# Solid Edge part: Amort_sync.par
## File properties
Author: KULL
Template: Iso Metric Part.par
Last saved by: KULL
Revision: 11
Application: Solid Edge
Accuracy: 0,990
Face Style: Model Default
Fill Style: Normal
Coef. of Thermal Exp: 0.0
Thermal Conductivity: 0.0
Specific Heat: 0.0
Modulus of Elasticity: 0.0
Poisson's Ratio: 0.0
Yield Stress: 0.0
Ultimate Stress: 0.0
Elongation: 0.0
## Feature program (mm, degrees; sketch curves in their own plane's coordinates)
base feature "unnamed BaseFeature 1"
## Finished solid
Body 1: sheet body, 2 faces, 39 edges, 38 vertices.
  Faces by surface: plane 2
  Edges by curve: line 21, circle 18
Body 2: solid body, 53 faces, 87 edges, 36 vertices.
  Faces by surface: torus 17, plane 16, cylinder 14, blend 4, sphere 2
  Edges by curve: circle 59, line 16, intersection 12
Bounding box of the edges (mm; curved faces can reach further): 16.000 x 31.352 x 49.821, from (-8, 49.3583, 6.9663) to (8, 80.7104, 56.7877).
Cylindrical faces by radius (mm): R0.8 x4, R1.5 x3, R2 x2, R3 x2, R4 x1, R8 x2
Toroidal faces (ring radius, tube radius in mm): R1.1 r0.4 x2, R2.2 r0.8 x2, R5.8516 r1.2 x2, R6 r4 x1, R7.2 r0.8 x2, R7.8 r0.2 x2, R21.2565 r0.8 x4, R23.3814 r0.8 x2
Spherical faces by radius (mm): R23.0491 x2
Planar faces by outward normal: +x 3, -x 3, oblique 10
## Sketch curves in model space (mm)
circle centre (0, 59.9207, 39.7682) radius 4
circle centre (0, 73.196, 15.5693) radius 3
line (0, 73.196, 15.5693) -> (0, 59.9207, 39.7682)
line (0, 66.5584, 27.6687) -> (0, 78.9436, 34.4631)
line (0, 76.2697, 9.9663) -> (0, 56.847, 45.3711)
line (1.5, 70.4123, 11.7087) -> (1.5, 77.9476, 15.8425)
line (1.5, 74.1129, 7.8811) -> (1.5, 70.4123, 11.7087)
arc centre (1.5, 76.2697, 9.9663) radius 3 from (1.5, 79.1872, 10.6649) through (1.5, 77.634, 7.2945) to (1.5, 74.1129, 7.8811)
line (1.5, 79.1872, 10.6649) -> (1.5, 77.9476, 15.8425)
line (0, 100.499, -0.9341) -> (0, 96.4207, -3.1714)
line (0, 86.4712, -8.6296) -> (0, 90.5495, -6.3923)
circle centre (0, 76.2697, 9.9663) radius 3
circle centre (0, 76.2697, 9.9663) radius 1.5
arc centre (0, 78.3263, 18.3837) radius 1.2 from (0, 79.3784, 18.9609) through (0, 78.872, 17.315) to (0, 77.2742, 17.8066)
line (0, 79.3784, 18.9609) -> (0, 80.2099, 19.417)
line (0, 80.2099, 19.417) -> (0, 80.8832, 18.1896)
arc centre (0, 63.4726, 33.2936) radius 23.0491 from (0, 74.5585, 13.0856) through (0, 77.9476, 15.3566) to (0, 80.8832, 18.1896)
line (0, 73.196, 15.5693) -> (0, 74.5585, 13.0856)
line (0, 73.196, 15.5693) -> (0, 77.2742, 17.8066)
line (0, 59.9207, 39.7682) -> (0, 63.999, 42.0055)
line (0, 58.5582, 42.2519) -> (0, 59.9207, 39.7682)
arc centre (0, 69.6441, 22.0439) radius 23.0491 from (0, 58.5582, 42.2519) through (0, 62.2946, 43.8898) to (0, 66.2613, 44.8434)
line (0, 66.9346, 43.6159) -> (0, 66.2613, 44.8434)
line (0, 66.1032, 43.1598) -> (0, 66.9346, 43.6159)
arc centre (0, 65.0511, 42.5826) radius 1.2 from (0, 66.1032, 43.1598) through (0, 64.443, 43.6171) to (0, 63.999, 42.0055)
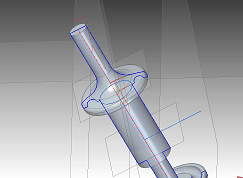
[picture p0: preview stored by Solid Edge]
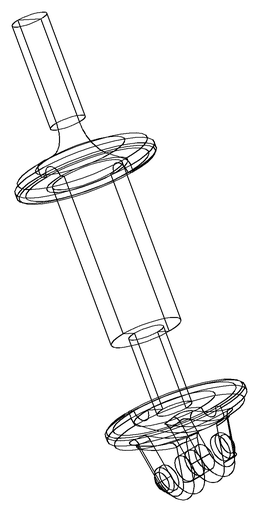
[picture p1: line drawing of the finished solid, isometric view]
